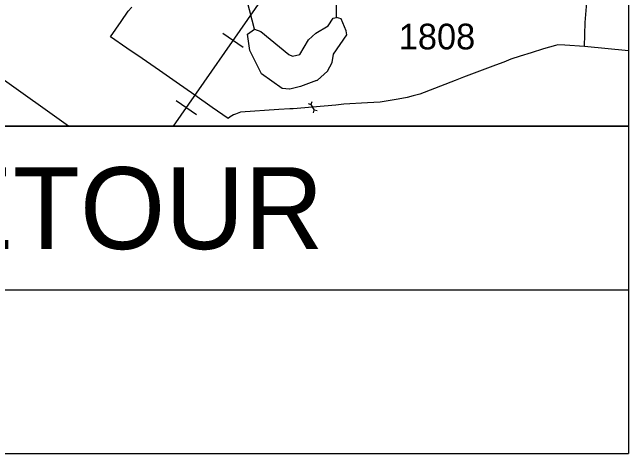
# Model space of a CAD drawing. Extents: x 0 to 2021, y 0 to 1321.
# Drawn here: x 541.9 to 654.8, y 888.1 to 969 of the extents above; entities that cross this region are included whole.
import ezdxf

# ---------------------------------------------------------------- set-up
doc = ezdxf.new("R2010")
doc.units = 0
for name, color, linetype in [('Default', 7, 'Continuous'), ('Exist Hydro Stream or Body of Water', 7, 'Continuous'), ('Miscellaneous Lines', 7, 'Continuous'), ('Old_Level_26', 7, 'Continuous'), ('Scratch_Level_0', 7, 'Continuous'), ('Sheet Data Field CELL', 7, 'Continuous'), ('Sheet Title CELL', 7, 'Continuous'), ('Text', 7, 'Continuous')]:
    doc.layers.add(name, color=color, linetype=linetype)

msp = doc.modelspace()

# ---------------------------------------------------------------- linework, layer by layer
at = {"layer": 'Default'}
for p, q in [((596.09, 952.23), (596.59, 952.1)), ((596.74, 952.59), (596.59, 952.1)), ((596.59, 952.1), (597.2, 951.04)), ((597.05, 950.54), (597.2, 951.04)), ((597.7, 950.91), (597.2, 951.04))]:
    msp.add_line(p, q, dxfattribs=at)
for points in [[(575.29, 953.78), (571.9, 956.15), (568.86, 958.28), (565.67, 960.51), (562.87, 962.39), (559.85, 964.5), (561.82, 967.32), (563.13, 969.18), (563.8, 969.91)], [(581.43, 949.51), (578.49, 951.53), (575.29, 953.78)]]:
    msp.add_lwpolyline(points, dxfattribs=at)
at = {"layer": 'Exist Hydro Stream or Body of Water'}
for points in [[(586.24, 965.89), (584.88, 971.1), (584.6, 976.16), (585.35, 979.14), (585.26, 981.23), (584.06, 984.35), (581.86, 987.98), (581.43, 989.32), (582.75, 996.34), (583.05, 1005.54), (584.37, 1013.73), (584.86, 1019.04), (585.45, 1020.42), (589.14, 1025.4), (588.87, 1028.53), (588.44, 1029.8), (588.1, 1032.23), (588.02, 1032.55)], [(601.26, 968.04), (601.25, 971.26), (602.5, 974.19), (603.58, 981.32), (605.34, 985.04), (609.04, 988.92), (609.88, 990.7), (610.28, 993.08), (611.87, 995.34), (613.31, 995.95), (616.94, 995.97), (617.62, 996.49), (619.56, 996.38), (621.17, 994.55), (621.93, 994.7), (622.85, 997.18), (624.44, 997.84), (625.97, 997.78)], [(586.24, 965.89), (587.43, 965.46), (592.52, 961.27), (593.18, 960.92), (594.54, 961.26), (596.13, 963.95), (597.47, 965.16), (599.75, 966.51), (600.68, 967.88), (601.26, 968.04)], [(597.62, 956.49), (597.76, 956.54), (599.62, 958.16), (600.45, 959.78), (600.7, 961.3), (603.14, 964.84), (603.05, 965.61), (602.12, 967.79), (601.26, 968.04)], [(592.63, 954.86), (591.28, 955.01), (587.55, 957.68), (585.41, 961.98), (584.99, 964.95), (586.24, 965.89)], [(597.62, 956.49), (594.65, 955.35), (594.65, 955.35)], [(594.65, 955.35), (592.7, 954.86), (592.63, 954.86)]]:
    msp.add_lwpolyline(points, dxfattribs=at)
at = {"layer": 'Miscellaneous Lines'}
for p, q in [((654.77, 1067.84), (571.32, 948.09)), ((580.45, 965.14), (584.17, 962.56)), ((571.89, 952.83), (575.61, 950.24))]:
    msp.add_line(p, q, dxfattribs=at)
msp.add_lwpolyline([(552.18, 948.09), (539.54, 957.1)], dxfattribs=at)
at = {"layer": 'Old_Level_26'}
for points in [[(646.69, 962.7), (646.83, 967.13), (647.15, 971.59), (647.4, 973.91), (647.69, 975.89), (648.1, 978.43), (648.25, 980.12)], [(646.69, 962.7), (643.09, 962.97), (641.83, 963), (641.39, 962.92), (639.2, 962.3), (636.9, 961.54), (634.88, 960.91), (633.21, 960.36), (631.88, 959.84), (630.37, 959.3), (624.51, 957.09), (622.97, 956.49), (616.54, 953.95), (615.3, 953.67), (614.18, 953.37), (612.55, 953.04), (609.99, 952.61), (609.28, 952.52), (606.94, 952.35), (602.58, 952.15), (601.12, 951.98), (596.89, 951.57), (593.32, 951.31), (592.71, 951.27), (590.72, 951.16), (583.66, 950.64), (582.76, 950.33), (582.4, 950.18), (581.8, 949.8), (581.43, 949.51)], [(654.77, 961.94), (646.69, 962.7)]]:
    msp.add_lwpolyline(points, dxfattribs=at)
at = {"layer": 'Scratch_Level_0'}
msp.add_lwpolyline([(318.71, 1236.23), (654.77, 1236.23), (654.77, 948.09), (318.71, 948.09)], close=True, dxfattribs=at)
at = {"layer": 'Sheet Title CELL'}
for p, q in [((654.77, 1236.23), (654.77, 888.06)), ((318.71, 948.09), (654.77, 948.09)), ((318.71, 918.07), (654.77, 918.07)), ((318.71, 888.06), (654.77, 888.06))]:
    msp.add_line(p, q, dxfattribs=at)

# ---------------------------------------------------------------- texts
at = {"layer": 'Sheet Data Field CELL'}
msp.add_text('DETOUR', height=15.007, rotation=360, dxfattribs=at).set_placement((514.14, 925.57))
at = {"layer": 'Text'}
msp.add_text('1808', height=4.705, rotation=360, dxfattribs=at).set_placement((612.67, 962.18))

doc.saveas('drawing.dxf')
